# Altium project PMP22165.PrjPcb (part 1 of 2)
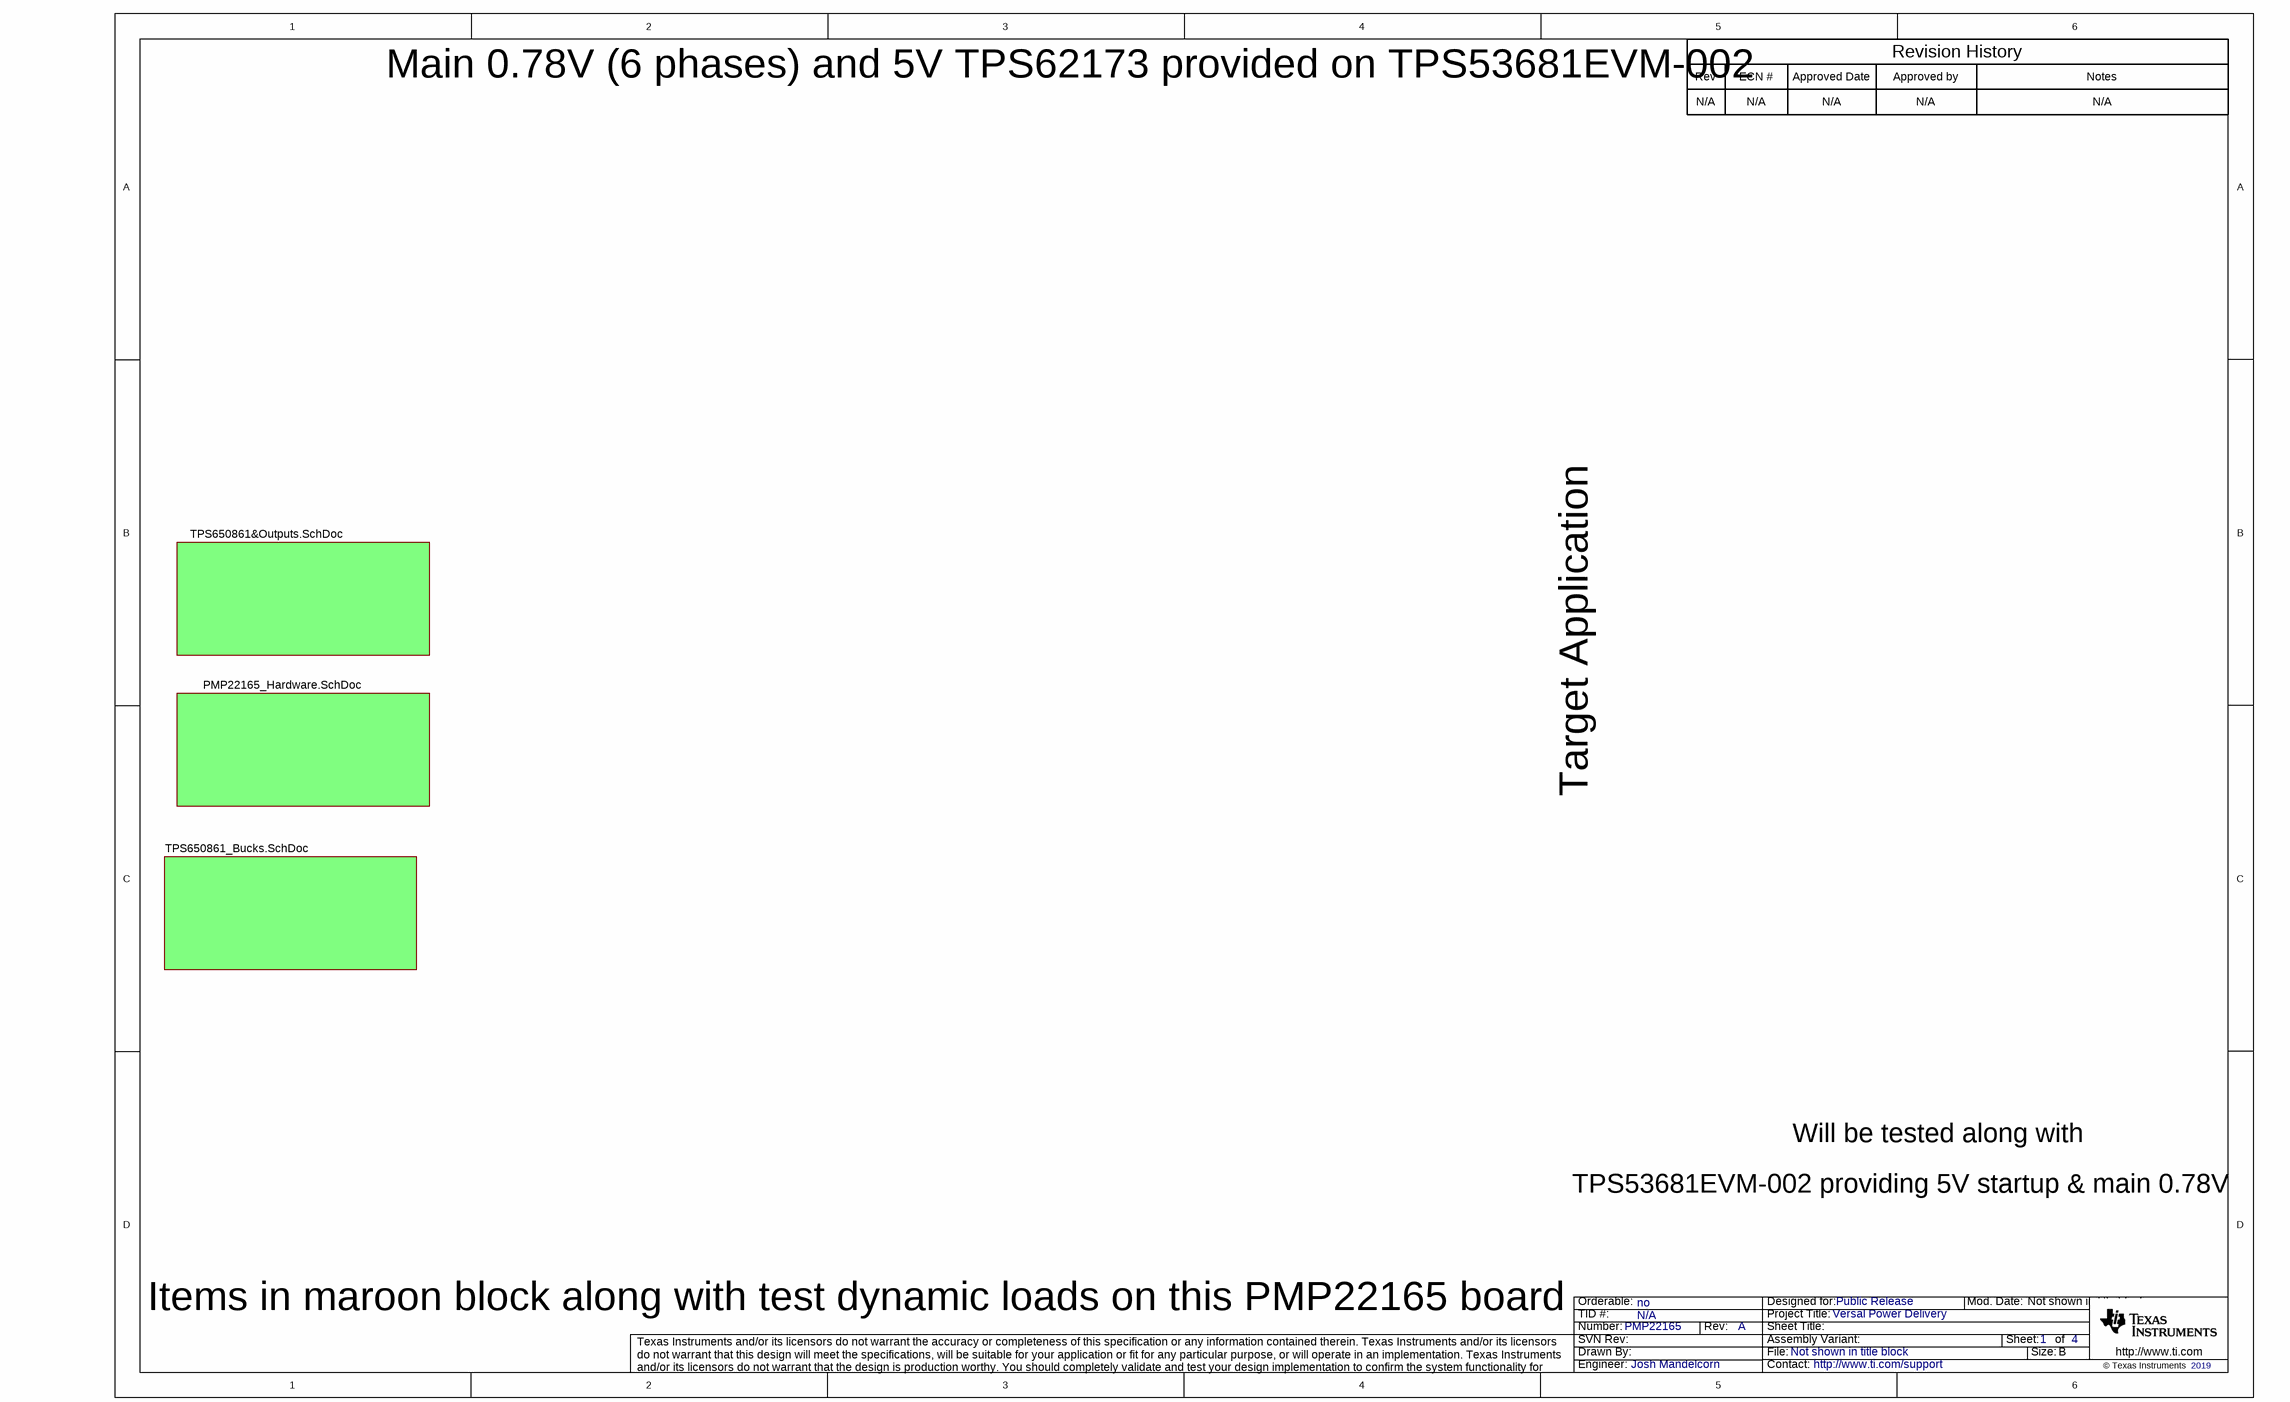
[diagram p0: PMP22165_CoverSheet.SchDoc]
CopyrightYear: 2019; EVM_orderable: no; PCB_Layout: TBD; PCB_Rev: A; PRJ_Customer: Public Release; PRJ_Engineer: Josh Mandelcorn; PRJ_Number: PMP22165; PRJ_Title: Versal Power Delivery; SCH_Rev: A; TechSupport: http://www.ti.com/support; TID: N/A
4 sheets, 234 parts. Net scope: flat (ports and power ports of the same name join across sheets).
Board file: PMP22165_PCB.PcbDoc
Sheets:
  PMP22165_CoverSheet.SchDoc
    Designator = TPS650861&Outputs.SchDoc
    Designator = PMP22165_Hardware.SchDoc
    Designator = TPS650861_Bucks.SchDoc

## Sheet PMP22165_CoverSheet.SchDoc
size 431 x 279 mm; Date: Not shown in title block; ApprovedBy: Not shown in title block; CheckedBy: Not shown in title block; Author: Not shown in title block; CompanyName: Not shown in title block; Engineer: Not shown in title block; Organization: Not shown in title block; Address1: Not shown in title block; Address2: Not shown in title block; Address3: Not shown in title block; Address4: Not shown in title block; DocumentNumber: 1; Revision: Use project parameter SCH_Rev; SheetNumber: 1; SheetTotal: 4; PageSetup: Record=PageOptions¦CenterHorizontal=True¦CenterVertical=True¦PrintScale=1.00¦XCorrection=1.00¦YCorrection=1.00¦PrintKind=0¦BorderSize=5000000¦LeftOffset=0¦BottomOffset=0¦Orientation=2¦PaperLength=1000¦PaperWidth=1000¦Scale=100¦PaperSource=15¦PrintQuality=600¦MediaType=1¦DitherType=10¦PaperKind=Letter¦PrintScaleMode=1

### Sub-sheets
Designator = TPS650861&Outputs.SchDoc: no entries
Designator = PMP22165_Hardware.SchDoc: no entries
Designator = TPS650861_Bucks.SchDoc: no entries

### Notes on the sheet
- Main 0.78V (6 phases) and 5V TPS62173 provided on TPS53681EVM-002
- Rev
- N/A
- ECN #
- Approved Date
- Approved by
- Revision History
- Notes
- Target Application
- Will be tested along with
- TPS53681EVM-002 providing 5V startup & main 0.78V
- Items in maroon block along with test dynamic loads on this PMP22165 board

## Sheet TPS650861&Outputs.SchDoc
size 431 x 279 mm; Date: Not shown in title block; ApprovedBy: Not shown in title block; CheckedBy: Not shown in title block; Author: Not shown in title block; CompanyName: Not shown in title block; Engineer: Not shown in title block; Organization: Not shown in title block; Address1: Not shown in title block; Address2: Not shown in title block; Address3: Not shown in title block; Address4: Not shown in title block; DocumentNumber: 2; Revision: Use project parameter SCH_Rev; SheetNumber: 2; SheetTotal: 4; PageSetup: Record=PageOptions¦CenterHorizontal=True¦CenterVertical=True¦PrintScale=1.00¦XCorrection=1.00¦YCorrection=1.00¦PrintKind=0¦BorderSize=5000000¦LeftOffset=0¦BottomOffset=0¦Orientation=2¦PaperLength=1000¦PaperWidth=1000¦Scale=100¦PaperSource=15¦PrintQuality=600¦MediaType=1¦DitherType=10¦PaperKind=Letter¦PrintScaleMode=1
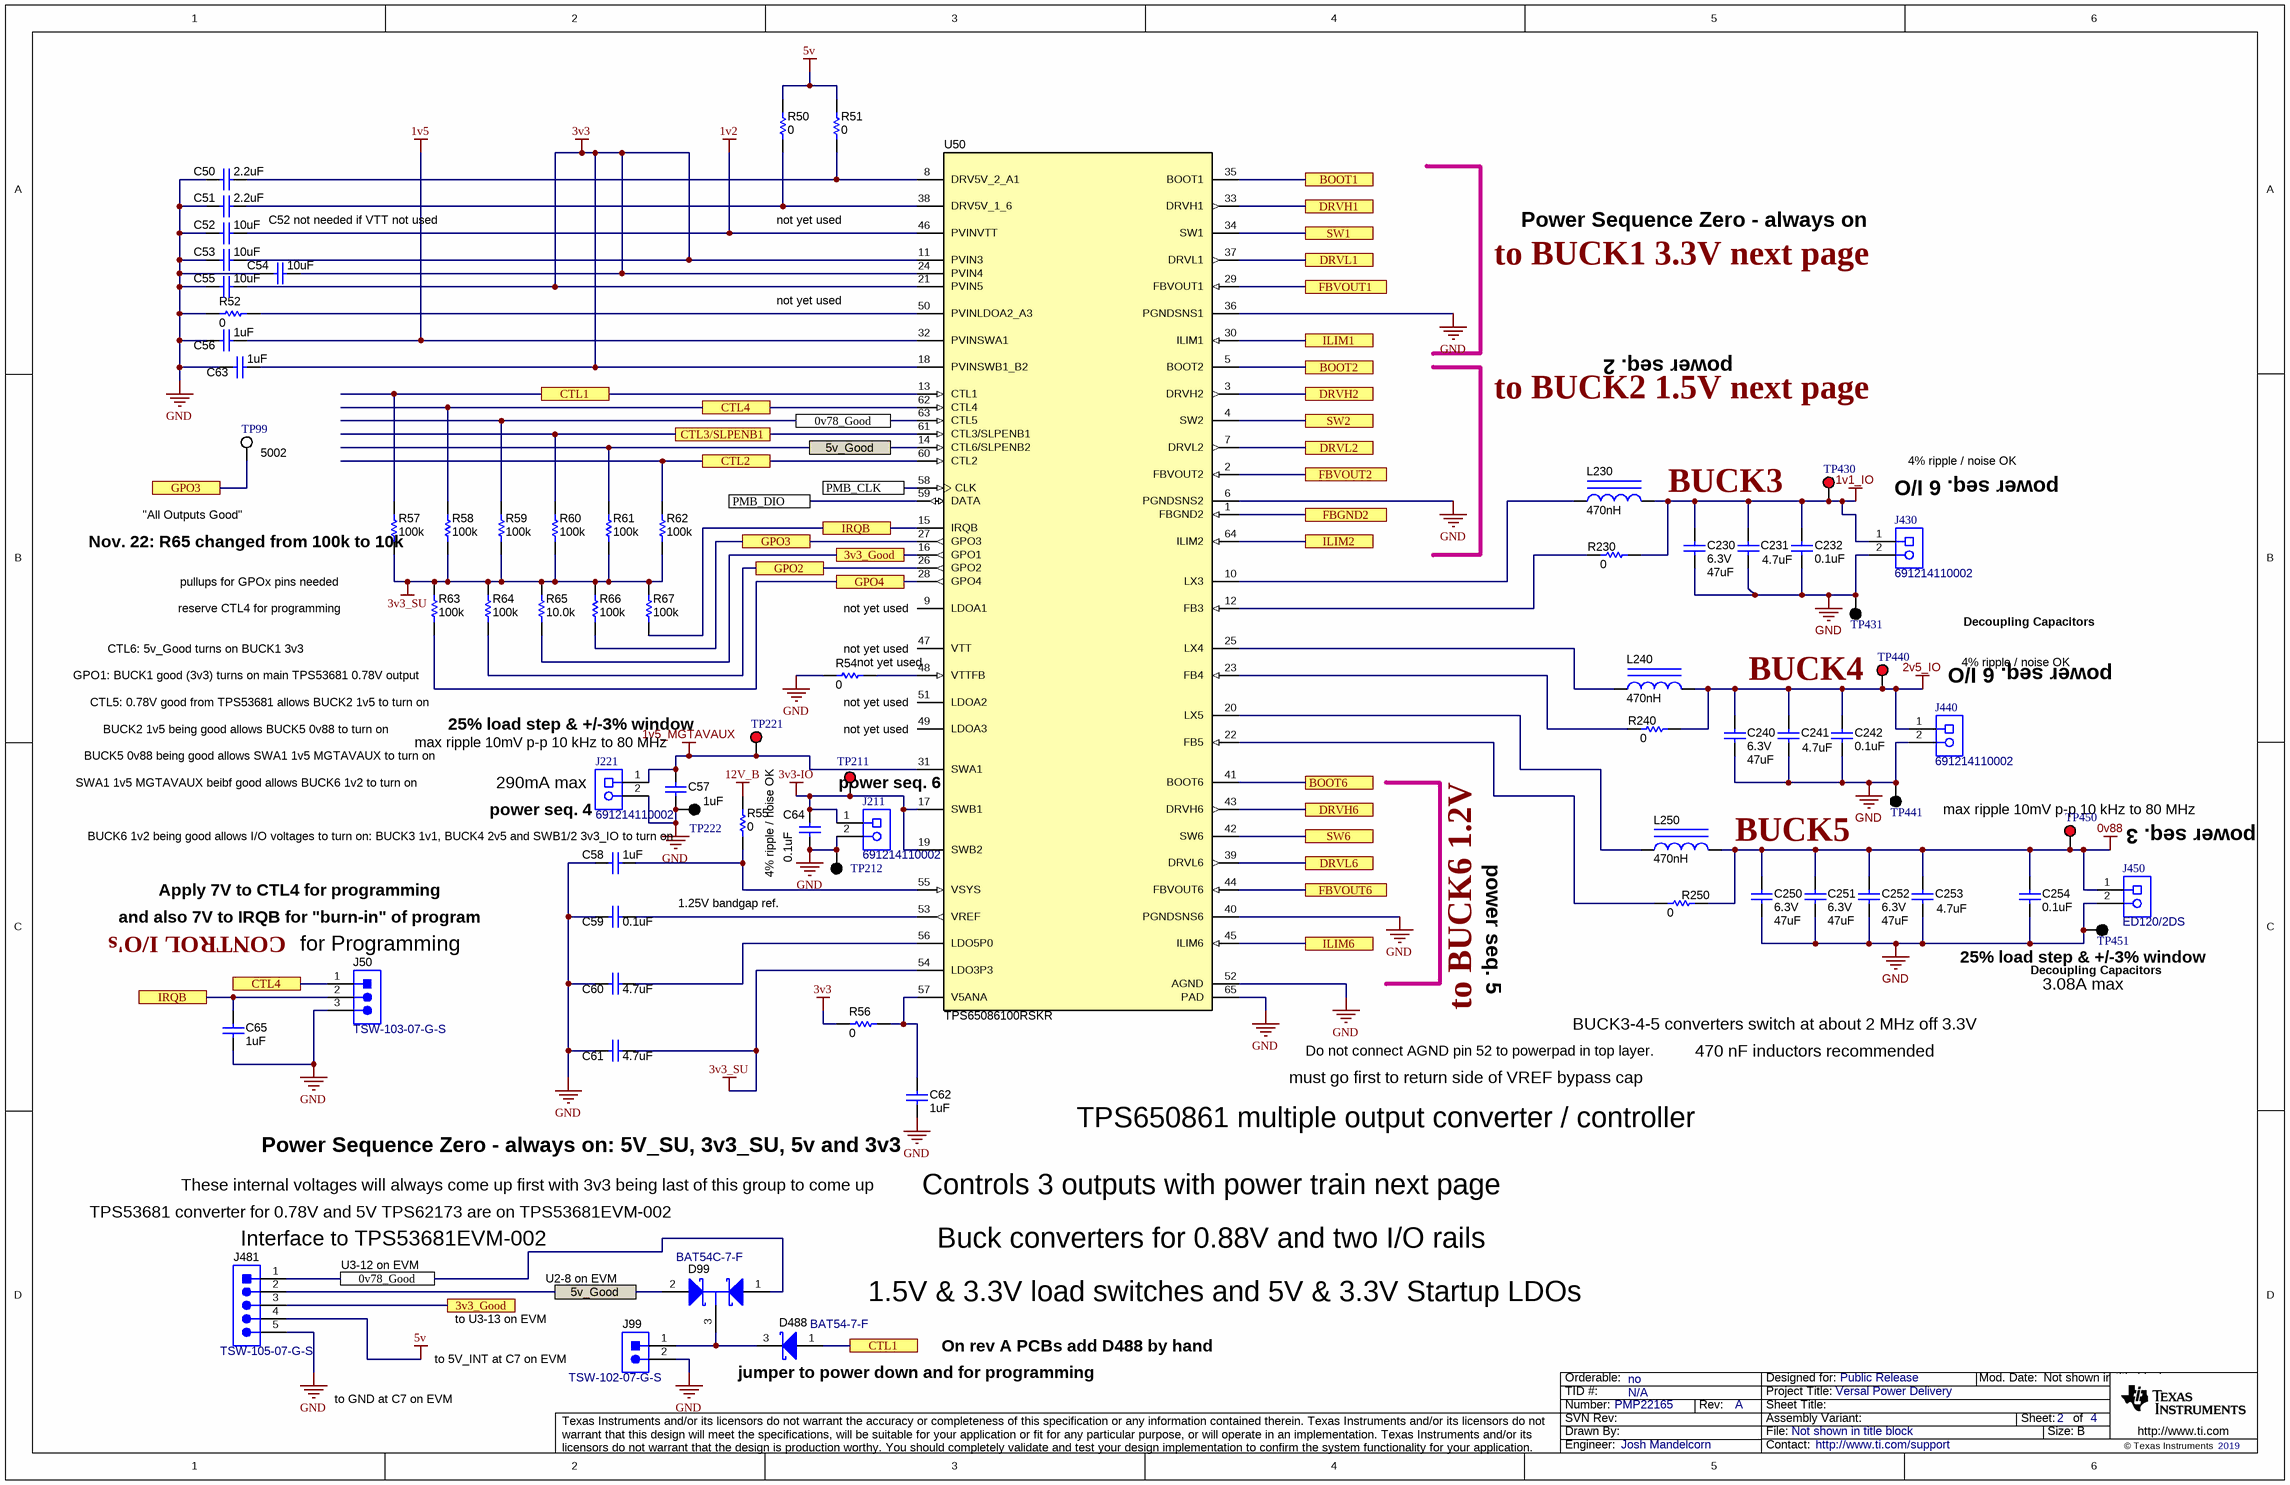
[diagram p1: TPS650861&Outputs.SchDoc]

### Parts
C50  ValueDisplayed: 2.2uF  [0402]  (hidden comment: Capacitor)
C51  ValueDisplayed: 2.2uF  [0402]  (hidden comment: Capacitor)
C52  ValueDisplayed: 10uF  [0402]  (hidden comment: GRM155R61A106ME11)
C53  ValueDisplayed: 10uF  [0402]  (hidden comment: GRM155R61A106ME11)
C54  ValueDisplayed: 10uF  [0402]  (hidden comment: GRM155R61A106ME11)
C55  ValueDisplayed: 10uF  [0402]  (hidden comment: GRM155R61A106ME11)
C56  ValueDisplayed: 1uF  [0402]  (hidden comment: Capacitor)
C57  ValueDisplayed: 1uF  [0402]  (hidden comment: Capacitor)
C58  ValueDisplayed: 1uF  [0402]  (hidden comment: Capacitor)
C59  ValueDisplayed: 0.1uF  [0402]  (hidden comment: Capacitor)
C60  ValueDisplayed: 4.7uF  [0603]  (hidden comment: Capacitor)
C61  ValueDisplayed: 4.7uF  [0603]  (hidden comment: Capacitor)
C62  ValueDisplayed: 1uF  [0402]  (hidden comment: Capacitor)
C63  ValueDisplayed: 1uF  [0402]  (hidden comment: Capacitor)
C64  ValueDisplayed: 0.1uF  [0402]  (hidden comment: Capacitor)
C65  ValueDisplayed: 1uF  [0402]  (hidden comment: Capacitor)
C230  VDC_V: 6.3V  ValueDisplayed: 47uF  [0805_HV]  (hidden comment: GRM21BR60J476ME15L)
C231  value 4.7uF  [0603]  (hidden comment: Capacitor)
C232  ValueDisplayed: 0.1uF  [0402]  (hidden comment: Capacitor)
C240  VDC_V: 6.3V  ValueDisplayed: 47uF  [0805_HV]  (hidden comment: GRM21BR60J476ME15L)
C241  value 4.7uF  [0603]  (hidden comment: Capacitor)
C242  ValueDisplayed: 0.1uF  [0402]  (hidden comment: Capacitor)
C250  VDC_V: 6.3V  ValueDisplayed: 47uF  [0805_HV]  (hidden comment: GRM21BR60J476ME15L)
C251  VDC_V: 6.3V  ValueDisplayed: 47uF  [0805_HV]  (hidden comment: GRM21BR60J476ME15L)
C252  VDC_V: 6.3V  ValueDisplayed: 47uF  [0805_HV]  (hidden comment: GRM21BR60J476ME15L)
C253  value 4.7uF  [0603]  (hidden comment: Capacitor)
C254  ValueDisplayed: 0.1uF  [0402]  (hidden comment: Capacitor)
D99  BAT54C-7-F  [SOT-23]
D488  BAT54-7-F  [SOT-23]
J50  TSW-103-07-G-S  [TSW-103-07-G-S]
J99  TSW-102-07-G-S  [TSW-102-07-G-S]
J211  691214110002  [Wurth_691214110002]
J221  691214110002  [Wurth_691214110002]
J430  691214110002  [Wurth_691214110002]
J440  691214110002  [Wurth_691214110002]
J450  ED120/2DS  [On-Shore_ED120_2DS]
J481  TSW-105-07-G-S  [TSW-105-07-X-S]
L230  ValueDisplayed: 470nH  [WE-MAPI_3020]  (hidden comment: 744383360047)
L240  ValueDisplayed: 470nH  [WE-MAPI_3020]  (hidden comment: 744383360047)
L250  ValueDisplayed: 470nH  [WE-MAPI_3020]  (hidden comment: 744383360047)
R50  ValueDisplayed: 0  [0402]  (hidden comment: Resistor)
R51  ValueDisplayed: 0  [0402]  (hidden comment: Resistor)
R52  ValueDisplayed: 0  [0402]  (hidden comment: Resistor)
R54  ValueDisplayed: 0  [0402]  (hidden comment: Resistor)
R55  ValueDisplayed: 0  [0402]  (hidden comment: Resistor)
R56  ValueDisplayed: 0  [0402]  (hidden comment: Resistor)
R57  Value_Code: 100k  [0402]  (hidden comment: Resistor)
R58  Value_Code: 100k  [0402]  (hidden comment: Resistor)
R59  Value_Code: 100k  [0402]  (hidden comment: Resistor)
R60  Value_Code: 100k  [0402]  (hidden comment: Resistor)
R61  Value_Code: 100k  [0402]  (hidden comment: Resistor)
R62  Value_Code: 100k  [0402]  (hidden comment: Resistor)
R63  Value_Code: 100k  [0402]  (hidden comment: Resistor)
R64  Value_Code: 100k  [0402]  (hidden comment: Resistor)
R65  ValueDisplayed: 10.0k  [0402]  (hidden comment: CRCW040210K0FKED)
R66  Value_Code: 100k  [0402]  (hidden comment: Resistor)
R67  Value_Code: 100k  [0402]  (hidden comment: Resistor)
R230  ValueDisplayed: 0  [0402]  (hidden comment: Resistor)
R240  ValueDisplayed: 0  [0402]  (hidden comment: Resistor)
R250  ValueDisplayed: 0  [0402]  (hidden comment: Resistor)
TP99  5002  [Keystone5002]
TP211  5000  [Keystone5000]  (value not drawn)
TP212  5001  [Keystone5001]  (value not drawn)
TP221  5000  [Keystone5000]  (value not drawn)
TP222  5001  [Keystone5001]  (value not drawn)
TP430  5000  [Keystone5000]  (value not drawn)
TP431  5001  [Keystone5001]  (value not drawn)
TP440  5000  [Keystone5000]  (value not drawn)
TP441  5001  [Keystone5001]  (value not drawn)
TP450  5000  [Keystone5000]  (value not drawn)
TP451  5001  [Keystone5001]  (value not drawn)
U50  TPS65086100RSKR  [RSK0064C]

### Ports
0v78_Good, 3v3_Good, 5v_Good, BOOT1, BOOT2, BOOT6, CTL1, CTL2, CTL3/SLPENB1, CTL4, DRVH1, DRVH2, DRVH6, DRVL1, DRVL2, DRVL6, FBGND2, FBVOUT1, FBVOUT2, FBVOUT6, GPO2, GPO3, GPO4, ILIM1, ILIM2, ILIM6, IRQB, PMB_CLK, PMB_DIO, SW1, SW2, SW6

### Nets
0v88: C250.1 C251.1 C252.1 C253.1 C254.1 J450.1 L250.2 R250.2 TP450.1
1v1_IO: C230.1 C231.1 C232.1 J430.1 L230.2 R230.2 TP430.1
1v2: C52.1 U50.46(PVINVTT)
1v5: C56.1 U50.32(PVINSWA1)
1v5_MGTAVAUX: C57.1 J221.1 TP221.1 U50.31(SWA1)
2v5_IO: C240.1 C241.1 C242.1 J440.1 L240.2 R240.2 TP440.1
3v3: C53.1 C54.1 C55.1 C63.1 R56.2 U50.11(PVIN3) U50.18(PVINSWB1_B2) U50.21(PVIN5) U50.24(PVIN4)
3v3-IO: C64.1 J211.1 TP211.1 U50.17(SWB1) U50.19(SWB2)
3v3_SU: C61.1 R57.2 R58.2 R59.2 R60.2 R61.2 R62.2 R63.1 R64.1 R65.2 R66.1 R67.1 U50.54(LDO3P3)
5v: J481.4 R50.1 R51.1
12V_B: R55.2
GND: C50.2 C51.2 C52.2 C53.2 C54.2 C55.2 C56.2 C57.2 C58.2 C59.2 C60.2 C61.2 C62.2 C63.2 C64.2 C65.2 C230.2 C231.2 C232.2 C240.2 C241.2 C242.2 C250.2 C251.2 C252.2 C253.2 C254.2 J50.3 J99.2 J211.2 J221.2 J430.2 J440.2 J450.2 J481.5 R52.2 R54.2 TP212.1 TP222.1 TP431.1 TP441.1 TP451.1 U50.6(PGNDSNS2) U50.36(PGNDSNS1) U50.40(PGNDSNS6) U50.52(AGND) U50.65(PAD)
0v78_Good: D99.1(A1) J481.1 R59.1 U50.63(CTL5) ; port 0v78_Good
3v3_Good: J481.3 R65.1 U50.16(GPO1) ; port 3v3_Good
5v_Good: D99.2(A2) J481.2 R61.1 U50.14(CTL6/SLPENB2) ; port 5v_Good
BOOT1: U50.35(BOOT1) ; port BOOT1
BOOT2: U50.5(BOOT2) ; port BOOT2
BOOT6: U50.41(BOOT6) ; port BOOT6
CTL1: D488.1(A) R57.1 U50.13(CTL1) ; port CTL1
CTL2: R62.1 U50.60(CTL2) ; port CTL2
CTL3/SLPENB1: R60.1 U50.61(CTL3/SLPENB1) ; port CTL3/SLPENB1
CTL4: J50.1 R58.1 U50.62(CTL4) ; port CTL4
DRVH1: U50.33(DRVH1) ; port DRVH1
DRVH2: U50.3(DRVH2) ; port DRVH2
DRVH6: U50.43(DRVH6) ; port DRVH6
DRVL1: U50.37(DRVL1) ; port DRVL1
DRVL2: U50.7(DRVL2) ; port DRVL2
DRVL6: U50.39(DRVL6) ; port DRVL6
FBGND2: U50.1(FBGND2) ; port FBGND2
FBVOUT1: U50.29(FBVOUT1) ; port FBVOUT1
FBVOUT2: U50.2(FBVOUT2) ; port FBVOUT2
FBVOUT6: U50.44(FBVOUT6) ; port FBVOUT6
GPO2: R64.2 U50.26(GPO2) ; port GPO2
GPO3: R66.2 TP99.1 U50.27(GPO3) ; port GPO3
GPO4: R63.2 U50.28(GPO4) ; port GPO4
ILIM1: U50.30(ILIM1) ; port ILIM1
ILIM2: U50.64(ILIM2) ; port ILIM2
ILIM6: U50.45(ILIM6) ; port ILIM6
IRQB: C65.1 J50.2 R67.2 U50.15(IRQB) ; port IRQB
PMB_CLK: U50.58(CLK) ; port PMB_CLK
PMB_DIO: U50.59(DATA) ; port PMB_DIO
SW1: U50.34(SW1) ; port SW1
SW2: U50.4(SW2) ; port SW2
SW6: U50.42(SW6) ; port SW6
NetC50_1: C50.1 R51.2 U50.8(DRV5V_2_A1)
NetC51_1: C51.1 R50.2 U50.38(DRV5V_1_6)
NetC58_1: C58.1 R55.1 U50.55(VSYS)
NetC59_1: C59.1 U50.53(VREF)
NetC60_1: C60.1 U50.56(LDO5P0)
NetC62_1: C62.1 R56.1 U50.57(V5ANA)
NetD99_3: D99.3(K) D488.3(K) J99.1
NetL230_1: L230.1 U50.10(LX3)
NetL240_1: L240.1 U50.25(LX4)
NetL250_1: L250.1 U50.20(LX5)
NetR52_1: R52.1 U50.50(PVINLDOA2_A3)
NetR54_1: R54.1 U50.48(VTTFB)
NetR230_1: R230.1 U50.12(FB3)
NetR240_1: R240.1 U50.23(FB4)
NetR250_1: R250.1 U50.22(FB5)

Not connected (* = marked no-connect by the designer): U50 9(LDOA1) 47(VTT) 49(LDOA3) 51(LDOA2)

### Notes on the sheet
- C52 not needed if VTT not used
- not yet used
- Power Sequence Zero - always on
- to BUCK1 3.3V next page
- power seq. 2
- to BUCK2 1.5V next page
- BUCK3
- 4% ripple / noise OK
- power seq. 6 I/O
- "All Outputs Good"
- (near R57) Nov. 22: R65 changed from 100k to 10k
- pullups for GPOx pins needed
- reserve CTL4 for programming
- (near U50) not yet used
- Decoupling Capacitors
- CTL6: 5v_Good turns on BUCK1 3v3
- (near R63) GPO1: BUCK1 good (3v3) turns on main TPS53681 0.78V output
- CTL5: 0.78V good from TPS53681 allows BUCK2 1v5 to turn on
- (near R54) not yet used
- BUCK4
- BUCK2 1v5 being good allows BUCK5 0v88 to turn on
- BUCK5 0v88 being good allows SWA1 1v5 MGTAVAUX to turn on
- (near TP221) 25% load step & +/-3% window
- max ripple 10mV p-p 10 kHz to 80 MHz
- SWA1 1v5 MGTAVAUX beibf good allows BUCK6 1v2 to turn on
- BUCK6 1v2 being good allows I/O voltages to turn on: BUCK3 1v1, BUCK4 2v5 and SWB1/2 3v3_IO to turn on
- power seq. 4
- (near J221) 290mA max
- power seq. 6
- (near TP450) max ripple 10mV p-p 10 kHz to 80 MHz
- power seq. 3
- Apply 7V to CTL4 for programming
- 1.25V bandgap ref.
- BUCK5
- CONTROL I/O's
- and also 7V to IRQB for "burn-in" of program
- (near J50) for Programming
- power seq. 5
- (near TP451) 25% load step & +/-3% window
- (near TP451) Decoupling Capacitors
- to BUCK6 1.2V
- BUCK3-4-5 converters switch at about 2 MHz off 3.3V
- (near TP451) 3.08A max
- must go first to return side of VREF bypass cap
- Do not connect AGND pin 52 to powerpad in top layer.
- 470 nF inductors recommended
- (near C62) Power Sequence Zero - always on: 5V_SU, 3v3_SU, 5v and 3v3
- TPS650861 multiple output converter / controller
- TPS53681 converter for 0.78V and 5V TPS62173 are on TPS53681EVM-002
- (near J481) Interface to TPS53681EVM-002
- These internal voltages will always come up first with 3v3 being last of this group to come up
- Controls 3 outputs with power train next page
- Buck converters for 0.88V and two I/O rails
- U3-12 on EVM
- U2-8 on EVM
- 1.5V & 3.3V load switches and 5V & 3.3V Startup LDOs
- to U3-13 on EVM
- to 5V_INT at C7 on EVM
- (near D488) jumper to power down and for programming
- On rev A PCBs add D488 by hand
- to GND at C7 on EVM

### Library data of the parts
C50 C51 = CMP-0006341-2: CAP, CERM, 2.2 uF, 6.3 V, +/- 10%, X5R, 0402; PartNumber: CL05A225KQ5NNNC; Manufacturer: Samsung; Polarized: N; Value: 2.2uF; U/M: EA; Cap_F: 2.2µF; Value1: Unknown; VDC_V: 6.3V; TaMin_C: -55°C; TaMax_C: 85°C; AEC Category: Q200; SizeArea_mm2: 0.5; SizeAreaWB_mm2: 3; SizeX_mm: 1; SizeZ_mm: 0.6
C52-C55 = CMP-0006564-2: CAP, CERM, 10 uF, 10 V, +/- 20%, X5R, 0402; Manufacturer: MuRata; TaMin_C: -55°C; Polarized: N; SizeAreaWB_mm2: 3; Value1: Unknown; U/M: EA; Value: 10uF; TaMax_C: 85°C; SizeZ_mm: 0.6; SizeX_mm: 1; SizeY_mm: 0.5; Value2: 10V; Cap_F: 10µF; AEC Category: Q200
C56 C57 C62 C63 C65 = CMP-0006563-2: CAP, CERM, 1 uF, 10 V, +/- 10%, X5R, 0402; PartNumber: GRM155R61A105KE15D; Manufacturer: MuRata; Polarized: N; Value: 1uF; U/M: EA; Cap_F: 1µF; Value1: Unknown; VDC_V: 10V; TaMin_C: -55°C; TaMax_C: 85°C; AEC Category: Q200; SizeArea_mm2: 0.5; SizeAreaWB_mm2: 3; SizeX_mm: 1; SizeZ_mm: 0.6
C58 = CMP-0006619-2: CAP, CERM, 1 uF, 35 V, +/- 10%, X5R, 0402; PartNumber: GRM155R6YA105KE11D; Manufacturer: MuRata; Polarized: N; Value: 1uF; U/M: EA; Cap_F: 1µF; Value1: Unknown; VDC_V: 35V; TaMin_C: -55°C; TaMax_C: 85°C; AEC Category: Q200; SizeArea_mm2: 0.5; SizeAreaWB_mm2: 3; SizeX_mm: 1; SizeZ_mm: 0.6
C59 C64 C232 C242 C254 = CMP-0006562-2: CAP, CERM, 0.1 uF, 10 V, +/- 10%, X5R, 0402; PartNumber: GRM155R61A104KA01D; Manufacturer: MuRata; Polarized: N; Value: 0.1uF; U/M: EA; Cap_F: 100nF; Value1: Unknown; VDC_V: 10V; TaMin_C: -55°C; TaMax_C: 85°C; AEC Category: Q200; SizeArea_mm2: 0.5; SizeAreaWB_mm2: 3; SizeX_mm: 1; SizeZ_mm: 0.6
C60 C61 = CMP-0007330-5: CAP, CERM, 4.7 uF, 10 V, +/- 20%, X5R, 0603; PartNumber: GRM188R61A475ME15; Manufacturer: MuRata; Polarized: N; Value: 4.7uF; U/M: EA; Cap_F: 4.7µF; Value1: Unknown; VDC_V: 10V; TaMin_C: -55°C; TaMax_C: 85°C; AEC Category: Q200; SizeArea_mm2: 1.28; SizeAreaWB_mm2: 4.68; SizeX_mm: 1.6; SizeY_mm: 0.8; SizeZ_mm: 1
C230 C240 C250-C252 = CMP-0008284-2: CAP, CERM, 47 uF, 6.3 V, +/- 20%, X5R, 0805; Manufacturer: MuRata; TaMin_C: -55°C; Polarized: N; SizeAreaWB_mm2: 6.75; Value1: Unknown; U/M: EA; Value: 47uF; TaMax_C: 85°C; SizeZ_mm: 1.45; SizeX_mm: 2; SizeY_mm: 1.25; Cap_Case: 0805; SizeArea_mm2: 2.5; Cap_F: 47µF; AEC Category: Q200
C231 C241 C253 = CMP-0007312-5: CAP, CERM, 4.7 uF, 6.3 V, +/- 20%, X5R, 0603; PartNumber: GRM188R60J475ME19D; Manufacturer: MuRata; Polarized: N; U/M: EA; Cap_F: 4.7µF; ESR_ohm: 1m; Value1: 0.001 ohm; VDC_V: 6.3V; TaMin_C: -55°C; TaMax_C: 85°C; AEC Category: Q200; SizeArea_mm2: 1.28; SizeAreaWB_mm2: 4.68; SizeX_mm: 1.6; SizeY_mm: 0.8; SizeZ_mm: 1
D99 = CMP-0028453-2: Diode, Schottky, 30 V, 0.2 A, SOT-23; Manufacturer: Diodes Inc.; Vr_V: 30V; Green_Lifecycle: Active; Vf_V: 650mV; Value: 30V; SizeZ_mm: 1.1; SizeAreaWB_mm2: 14; TJmax_C: 125°C; Io_A: 200mA; Value2: 0.65V; SizeY_mm: 3; AEC Category: Q101; SizeX_mm: 2.5; Green_REACh: Passed; Value1: 0.2A; SizeArea_mm2: 7.5
D488 = CMP-0028451-1: Diode, Schottky, 30 V, 0.2 A, SOT-23; Manufacturer: Diodes Inc.; Io_A: 200mA; Green_Lifecycle: Active; SizeAreaWB_mm2: 14; Vr_V: 30V; Green_REACh: Passed; Value1: 0.2A; TJmax_C: 125°C; U/M: EA; Value: 30V; SizeZ_mm: 1.1; SizeX_mm: 2.5; SizeY_mm: 3; Vf_V: 650mV; Value2: 0.65V; SizeArea_mm2: 7.5; AEC Category: Q101
J50 = CMP-0075407-2: Header, 100mil, 3x1, Gold, TH; Manufacturer: Samtec; Pitch_mm: 2.54; Cert_VDE: N; Gender: Male; Cert_CSA: Y; Voltage_V: 550V; Green_REACh: Passed; Current_A: 6.3A; Green_Lifecycle: Active; Row_Count: 1
J99 = CMP-0075405-3: Header, 100mil, 2x1, Gold, TH; Manufacturer: Samtec; Current_A: 6.3A; Green_Lifecycle: Active; Pitch_mm: 2.54; Cert_CSA: Y; Cert_VDE: N; Green_REACh: Passed; Row_Count: 1; Gender: Male; Voltage_V: 550V
J211 J221 J430 J440 = CMP-0054825-2: Terminal Block, 3.5mm, 2x1, Tin, TH; Manufacturer: Wurth Elektronik; Pitch_mm: 3.5; CT: TRUE; CNHeader: FALSE; Voltage_V: 300V; Gender: Female; Cert_UL: Y; Row_Count: 1; Current_A: 10A
J450 = CMP-0074910-1: Terminal Block, 5.08 mm, 2x1, Brass, TH; Manufacturer: On-Shore Technology; Cert_VDE: Y; CNHeader: False; Current_A: 15A; Green_Lifecycle: Not Set; Shrouded: N; Gender: Female; Green_REACh: Incomplete; Voltage_V: 300V; Row_Count: 1; Pitch_mm: 5.08; CT: True
J481 = CMP-0075411-1: Header, 100mil, 5x1, Gold, TH; Manufacturer: Samtec; Pitch_mm: 2.54; Cert_VDE: N; Gender: Male; Cert_CSA: Y; Voltage_V: 550V; Green_REACh: Passed; Current_A: 6.3A; CT: False; Green_Lifecycle: Active; Row_Count: 1; CNHeader: True
L230 L240 L250 = CMP-0064156-1: Inductor, Wirewound, 470 nH, 4.8 A, 0.018 ohm, SMD; Manufacturer: Wurth Elektronik; Isat: 8A @ 20% inductance drop; Irms: 4.8A @ 40C rise; Green_Lifecycle: Active; SizeAreaWB_mm2: 16; DCR_ohm: 0.018; Green_REACh: Passed; Value: 470nH; Imax_A: 4.8A; SizeZ_mm: 2; SizeX_mm: 3; SizeArea_mm2: 9; AEC Qualified: N; AEC Category: Q200
R50-R52 R54-R56 R230 R240 R250 = CMP-0026822-3: RES, 0, 5%, 0.063 W, AEC-Q200 Grade 0, 0402; PartNumber: CRCW04020000Z0ED; Manufacturer: Vishay-Dale; Value: 0; Value_Code: 0000; Power_W: 63mW; Value2: 0.063W; VDC_V: 50V; TempCo: 200 ppm/C; EIA_Code: E24; AEC Category: Q200; AEC Qualified: Y; SizeArea_mm2: 0.5; SizeX_mm: 1; SizeZ_mm: 0.6
R57-R64 R66 R67 = CMP-0026823-3: RES, 100 k, 5%, 0.063 W, AEC-Q200 Grade 0, 0402; PartNumber: CRCW0402100KJNED; Manufacturer: Vishay-Dale; Value: 100k; Power_W: 63mW; Value2: 0.063W; VDC_V: 50V; TempCo: 200 ppm/C; EIA_Code: E24; AEC Category: Q200; AEC Grade: 0; AEC Qualified: Y; SizeArea_mm2: 0.5; SizeX_mm: 1; SizeZ_mm: 0.6
R65 = CMP-0025958-3: RES, 10.0 k, 1%, 0.063 W, AEC-Q200 Grade 0, 0402; Manufacturer: Vishay-Dale; Power_W: 63mW; TempCo: 100 ppm/C; Value_Code: 10k0; Value: 10.0k; EIA_Code: E96; Res_ohm: 10k; SizeX_mm: 1; SizeY_mm: 0.5; SizeZ_mm: 0.6; Value2: 0.063W; AEC Qualified: Y; VDC_V: 50V; AEC Category: Q200; AEC Grade: 0
TP99 = CMP-0055139-1: Test Point, Miniature, White, TH; Manufacturer: Keystone; CNHeader: FALSE; Green_Lifecycle: Active; Green_REACh: Passed; ContactFinish: Silver; CT: TRUE
TP211 TP221 TP430 TP440 TP450 = CMP-0055137-1: Test Point, Miniature, Red, TH; Manufacturer: Keystone; CNHeader: FALSE; Green_Lifecycle: Active; Green_REACh: Passed; ContactFinish: Silver; CT: TRUE
TP212 TP222 TP431 TP441 TP451 = CMP-0055138-1: Test Point, Miniature, Black, TH; Manufacturer: Keystone; CNHeader: FALSE; Green_Lifecycle: Active; Green_REACh: Passed; ContactFinish: Silver; CT: TRUE
U50 = CMP-0079628-1: Configurable Multi-Rail PMIC for 2S & 3S Li-Ion Battery-Operated Devices or Non Battery Operated, RSK0064C (VQFN-64); Alternate PartNumber: TPS65086100RSKT; Alternate Manufacturer: Texas Instruments; SizeAreaWB_mm2: 100; SizeZ_mm: 1; SizeX_mm: 8; SizeArea_mm2: 64; CompType: IC; AEC Qualified: N; AEC Category: Q200

## Sheet PMP22165_Hardware.SchDoc
size 431 x 279 mm; Date: Not shown in title block; ApprovedBy: Not shown in title block; CheckedBy: Not shown in title block; Author: Not shown in title block; CompanyName: Not shown in title block; Engineer: Not shown in title block; Organization: Not shown in title block; Address1: Not shown in title block; Address2: Not shown in title block; Address3: Not shown in title block; Address4: Not shown in title block; DocumentNumber: 4; Revision: Use project parameter SCH_Rev; SheetNumber: 4; SheetTotal: 4; PageSetup: Record=PageOptions¦CenterHorizontal=True¦CenterVertical=True¦PrintScale=1.00¦XCorrection=1.00¦YCorrection=1.00¦PrintKind=0¦BorderSize=5000000¦LeftOffset=0¦BottomOffset=0¦Orientation=2¦PaperLength=1000¦PaperWidth=1000¦Scale=100¦PaperSource=15¦PrintQuality=600¦MediaType=1¦DitherType=10¦PaperKind=Letter¦PrintScaleMode=1
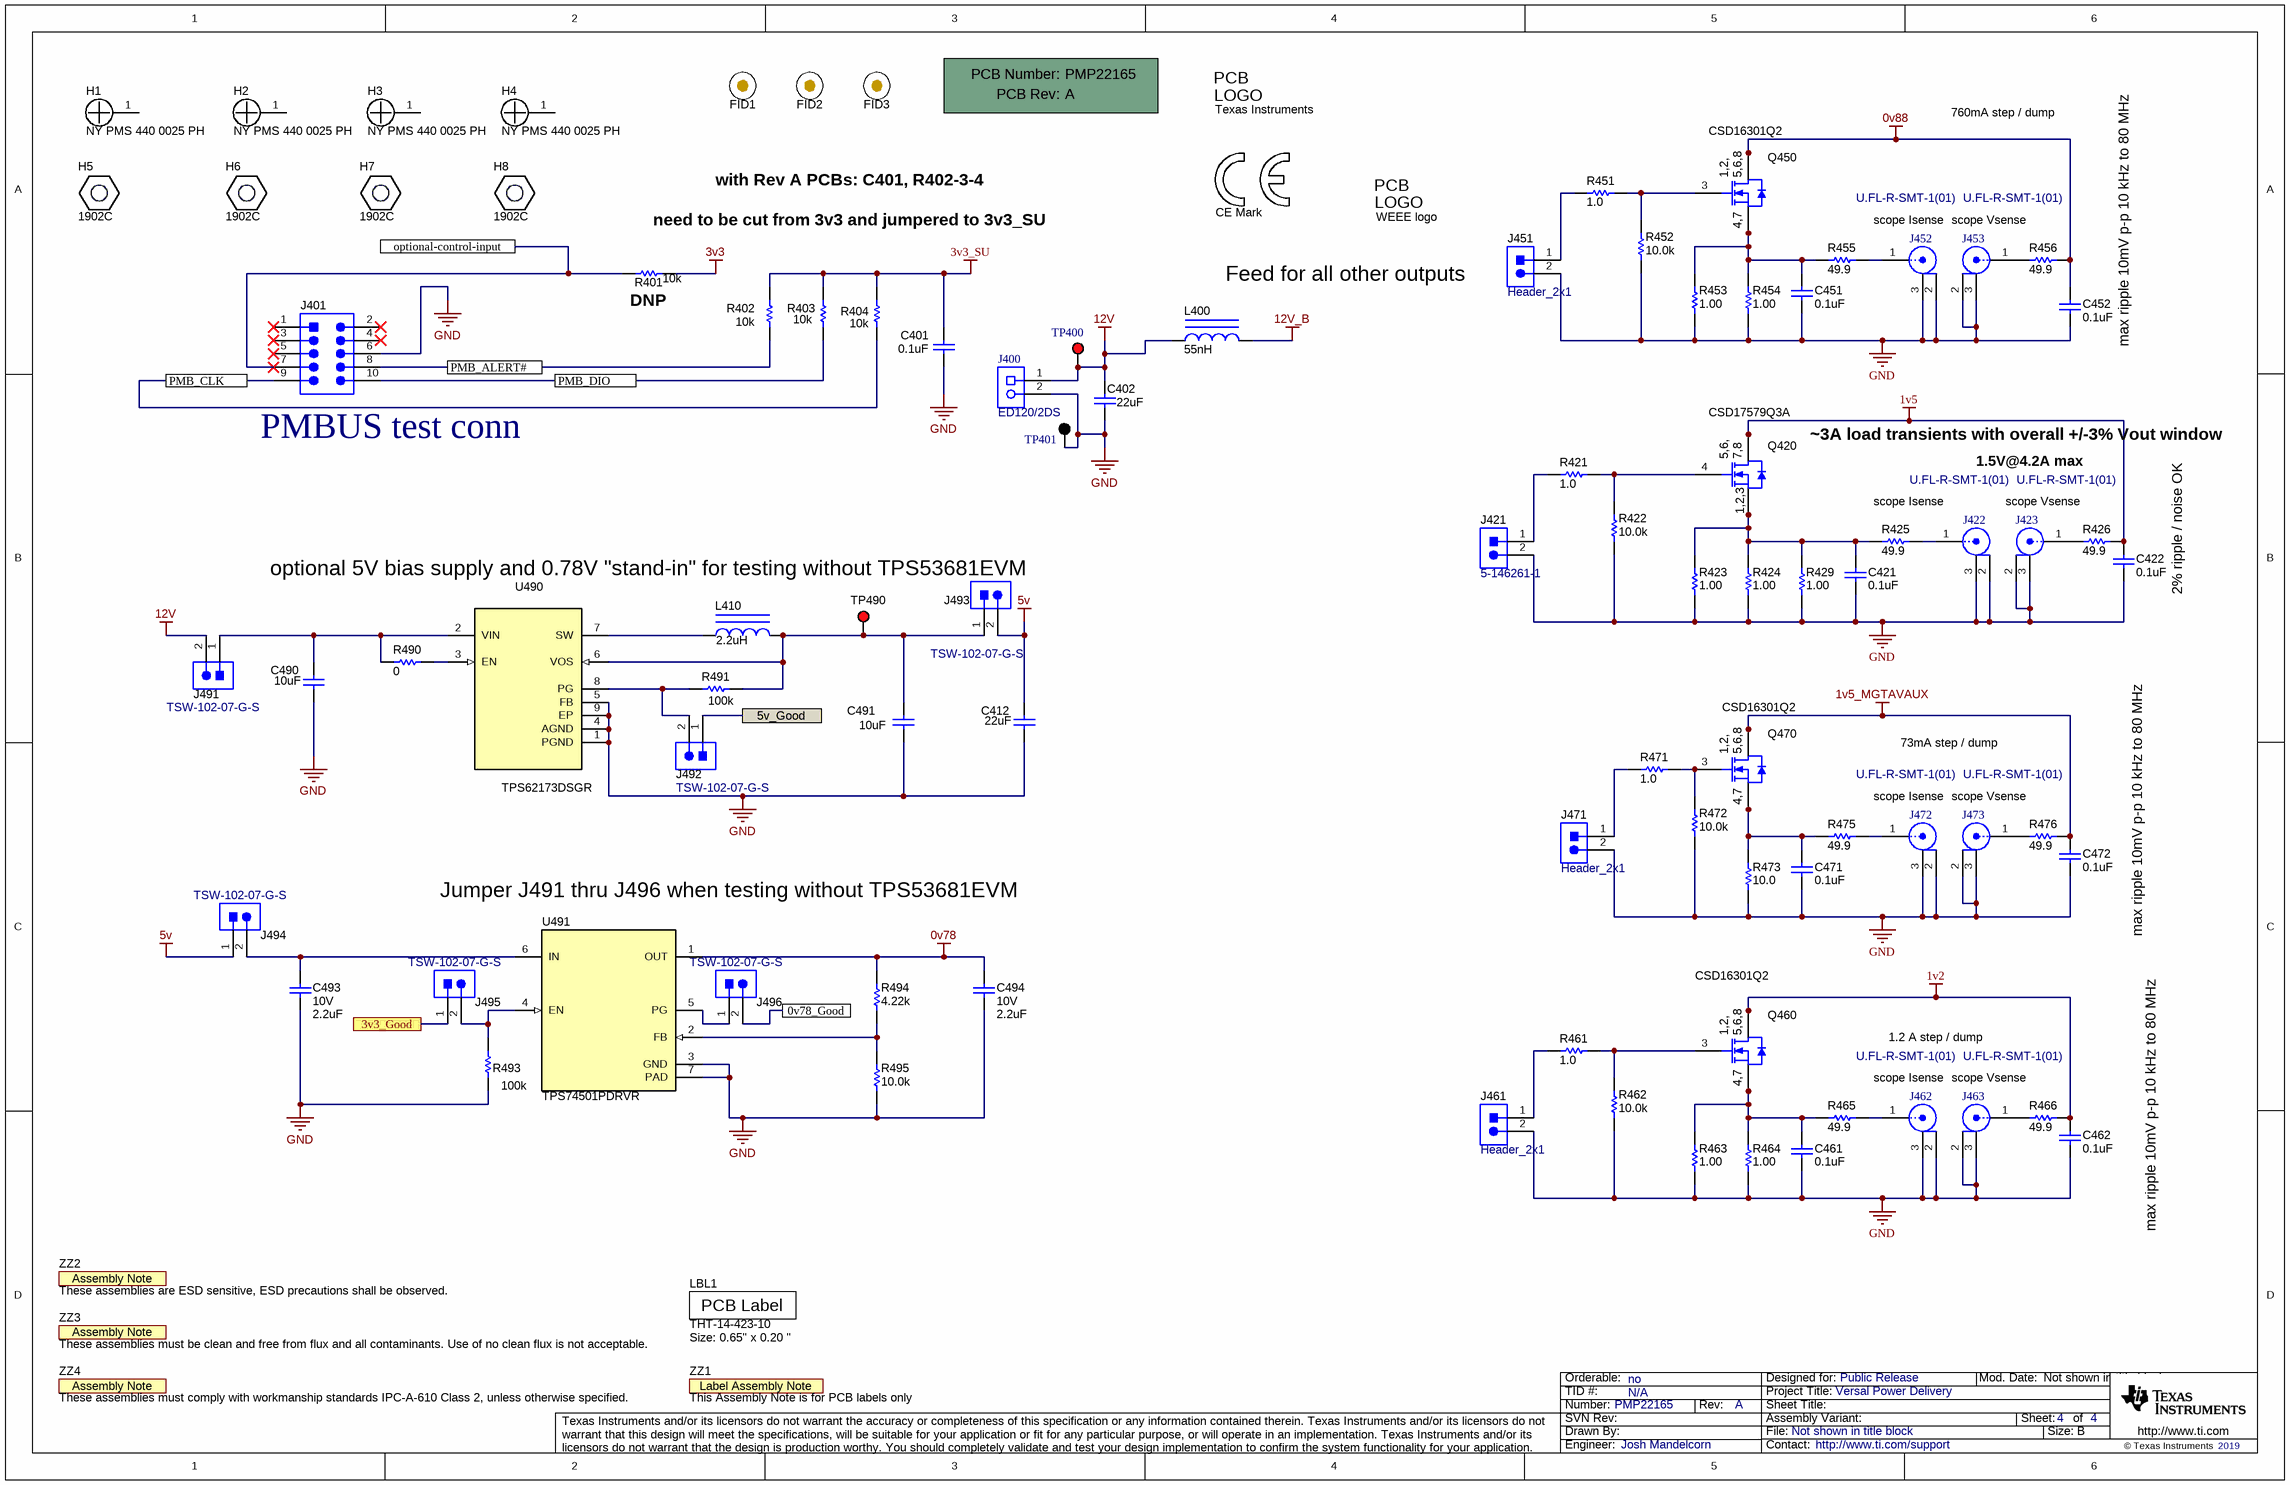
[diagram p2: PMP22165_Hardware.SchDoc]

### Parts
!PCB  Printed Circuit Board  (value not drawn)  (mechanical)
C401  ValueDisplayed: 0.1uF  [0603]  (hidden comment: 06035C104KAT2A)
C402  ValueDisplayed: 22uF  [1206_180]  (hidden comment: GRM31CR61C226KE15L)
C412  ValueDisplayed: 22uF  [0805_HV]  (hidden comment: C2012X5R0J226M085AB)
C421  ValueDisplayed: 0.1uF  [0402]  (hidden comment: GCM155R71H104KE02D)
C422  ValueDisplayed: 0.1uF  [0402]  (hidden comment: GCM155R71H104KE02D)
C451  ValueDisplayed: 0.1uF  [0402]  (hidden comment: Capacitor)
C452  ValueDisplayed: 0.1uF  [0402]  (hidden comment: GCM155R71H104KE02D)
C461  ValueDisplayed: 0.1uF  [0402]  (hidden comment: Capacitor)
C462  ValueDisplayed: 0.1uF  [0402]  (hidden comment: Capacitor)
C471  ValueDisplayed: 0.1uF  [0402]  (hidden comment: Capacitor)
C472  ValueDisplayed: 0.1uF  [0402]  (hidden comment: Capacitor)
C490  ValueDisplayed: 10uF  [0603]  (hidden comment: C1608X5R1E106M080AC)
C491  ValueDisplayed: 10uF  [0805]  (hidden comment: C2012X5R1E106K125AB)
C493  VDC_V: 10V  ValueDisplayed: 2.2uF  [0603]  (hidden comment: CGA3E3X5R1A225K080AB)
C494  VDC_V: 10V  ValueDisplayed: 2.2uF  [0603]  (hidden comment: CGA3E3X5R1A225K080AB)
FID1  Fiducial  [Fiducial10-20]  (value not drawn)
FID2  Fiducial  [Fiducial10-20]  (value not drawn)
FID3  Fiducial  [Fiducial10-20]  (value not drawn)
H1  NY PMS 440 0025 PH  [NY PMS 440 0025 PH]
H2  NY PMS 440 0025 PH  [NY PMS 440 0025 PH]
H3  NY PMS 440 0025 PH  [NY PMS 440 0025 PH]
H4  NY PMS 440 0025 PH  [NY PMS 440 0025 PH]
H5  1902C  [Keystone_1902C]
H6  1902C  [Keystone_1902C]
H7  1902C  [Keystone_1902C]
H8  1902C  [Keystone_1902C]
J400  ED120/2DS  [On-Shore_ED120_2DS]
J401  TSW-105-07-G-D  [TSW-105-07-G-D]  (value not drawn)
J421  5-146261-1  [CONN_5-146261-1]
J422  U.FL-R-SMT-1(01)  [CONN_UFL-R-SMT-1]
J423  U.FL-R-SMT-1(01)  [CONN_UFL-R-SMT-1]
J451  Header_2x1  [CONN_5-146261-1]
J452  U.FL-R-SMT-1(01)  [CONN_UFL-R-SMT-1]
J453  U.FL-R-SMT-1(01)  [CONN_UFL-R-SMT-1]
J461  Header_2x1  [CONN_5-146261-1]
J462  U.FL-R-SMT-1(01)  [CONN_UFL-R-SMT-1]
J463  U.FL-R-SMT-1(01)  [CONN_UFL-R-SMT-1]
J471  Header_2x1  [CONN_5-146261-1]
J472  U.FL-R-SMT-1(01)  [CONN_UFL-R-SMT-1]
J473  U.FL-R-SMT-1(01)  [CONN_UFL-R-SMT-1]
J491  TSW-102-07-G-S  [TSW-102-07-G-S]
J492  TSW-102-07-G-S  [TSW-102-07-G-S]
J493  TSW-102-07-G-S  [TSW-102-07-G-S]
J494  TSW-102-07-G-S  [TSW-102-07-G-S]
J495  TSW-102-07-G-S  [TSW-102-07-G-S]
J496  TSW-102-07-G-S  [TSW-102-07-G-S]
L400  ValueDisplayed: 55nH  [HCB65-550X]  (hidden comment: HCB65-550X)
L410  ValueDisplayed: 2.2uH  [XPL2010]  (hidden comment: XPL2010-222MLB)
LBL1  THT-14-423-10  Note: Size: 0.65" x 0.20 "  [Label_650x200]
Logo1  Texas Instruments  [TI_Stacked_Overlay_Small]  (no BOM)
Logo2  CE Mark  [CE_Mark_5mm]  (no BOM)
Logo4  WEEE logo  [WEEE_Minimum]  (no BOM)
Q420  PartNumber: CSD17579Q3A  [DNH0008A]  (hidden comment: MOSFET_N_D56789G4S123)
Q450  PartNumber: CSD16301Q2  [DQK0006C]  (hidden comment: MOSFET_N_D12568G3S47)
Q460  PartNumber: CSD16301Q2  [DQK0006C]  (hidden comment: MOSFET_N_D12568G3S47)
Q470  PartNumber: CSD16301Q2  [DQK0006C]  (hidden comment: MOSFET_N_D12568G3S47)
R401  value 10k  [0603]  (hidden comment: CRCW060310K0JNEA)
R402  value 10k  [0603]  (hidden comment: CRCW060310K0JNEA)
R403  value 10k  [0603]  (hidden comment: CRCW060310K0JNEA)
R404  value 10k  [0603]  (hidden comment: CRCW060310K0JNEA)
R421  ValueDisplayed: 1.0  [0402]  (hidden comment: Resistor)
R422  ValueDisplayed: 10.0k  [0402]  (hidden comment: Resistor)
R423  ValueDisplayed: 1.00  [1206]  (hidden comment: Resistor)
R424  ValueDisplayed: 1.00  [1206]  (hidden comment: Resistor)
R425  ValueDisplayed: 49.9  [0402]  (hidden comment: Resistor)
R426  ValueDisplayed: 49.9  [0402]  (hidden comment: Resistor)
R429  ValueDisplayed: 1.00  [1206]  (hidden comment: Resistor)
R451  ValueDisplayed: 1.0  [0402]  (hidden comment: Resistor)
R452  ValueDisplayed: 10.0k  [0402]  (hidden comment: Resistor)
R453  ValueDisplayed: 1.00  [1206]  (hidden comment: Resistor)
R454  ValueDisplayed: 1.00  [1206]  (hidden comment: Resistor)
R455  ValueDisplayed: 49.9  [0402]  (hidden comment: Resistor)
R456  ValueDisplayed: 49.9  [0402]  (hidden comment: Resistor)
R461  ValueDisplayed: 1.0  [0402]  (hidden comment: Resistor)
R462  ValueDisplayed: 10.0k  [0402]  (hidden comment: Resistor)
R463  ValueDisplayed: 1.00  [1206]  (hidden comment: Resistor)
R464  ValueDisplayed: 1.00  [1206]  (hidden comment: Resistor)
R465  ValueDisplayed: 49.9  [0402]  (hidden comment: Resistor)
R466  ValueDisplayed: 49.9  [0402]  (hidden comment: Resistor)
R471  ValueDisplayed: 1.0  [0402]  (hidden comment: Resistor)
R472  ValueDisplayed: 10.0k  [0402]  (hidden comment: Resistor)
R473  ValueDisplayed: 10.0  [1206]  (hidden comment: CRCW120610R0FKEA)
R475  ValueDisplayed: 49.9  [0402]  (hidden comment: CRCW040249R9FKED)
R476  ValueDisplayed: 49.9  [0402]  (hidden comment: CRCW040249R9FKED)
R490  ValueDisplayed: 0  [0603]  (hidden comment: CRCW06030000Z0EA)
R491  ValueDisplayed: 100k  [0603]  (hidden comment: CRCW0603100KFKEA)
R493  ValueDisplayed: 100k  [0603]  (hidden comment: CRCW0603100KFKEA)
R494  ValueDisplayed: 4.22k  [0402]  (hidden comment: CRCW04024K22FKED)
R495  ValueDisplayed: 10.0k  [0402]  (hidden comment: CRCW040210K0FKED)
TP400  5000  [Keystone5000]  (value not drawn)
TP401  5001  [Keystone5001]  (value not drawn)
TP490  (no value)  [Keystone5005]
U490  TPS62173DSGR  [DSG0008A]
U491  TPS74501PDRVR  [DRV0006A]
ZZ1  This Assembly Note is for PCB labels only  [AssemblyNoteLabel]  (no BOM)
ZZ2  These assemblies are ESD sensitive, ESD precautions shall be observed.  [AssemblyNote]  (no BOM)
ZZ3  These assemblies must be clean and free from flux and all contaminants. Use of no clean flux is not acceptable.  [AssemblyNote]  (no BOM)
ZZ4  These assemblies must comply with workmanship standards IPC-A-610 Class 2, unless otherwise specified.  [AssemblyNote]  (no BOM)

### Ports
0v78_Good, 3v3_Good, 5v_Good, optional-control-input, PMB_ALERT#, PMB_CLK, PMB_DIO

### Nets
0v78: C494.1 R494.2 U491.1(OUT)
0v88: C452.1 Q450.1(D) Q450.2(D) Q450.5(D) Q450.6(D) Q450.8(D) R456.2
1v2: C462.1 Q460.1(D) Q460.2(D) Q460.5(D) Q460.6(D) Q460.8(D) R466.2
1v5: C422.1 Q420.5(D) Q420.6(D) Q420.7(D) Q420.8(D) Q420.9(D) R426.2
1v5_MGTAVAUX: C472.1 Q470.1(D) Q470.2(D) Q470.5(D) Q470.6(D) Q470.8(D) R476.2
3v3: R401.2
3v3_SU: C401.1 R402.2 R403.2 R404.2
5v: C412.1 J493.2 J494.1
12V: C402.2 J400.1 J491.2 L400.1 TP400.1
12V_B: L400.2
GND: C401.2 C402.1 C412.2 C421.2 C422.2 C451.2 C452.2 C461.2 C462.2 C471.2 C472.2 C490.2 C491.2 C493.2 C494.2 J400.2 J401.6 J421.2 J422.2 J422.3 J423.2 J423.3 J451.2 J452.2 J452.3 J453.2 J453.3 J461.2 J462.2 J462.3 J463.2 J463.3 J471.2 J472.2 J472.3 J473.2 J473.3 R422.1 R423.1 R424.1 R429.1 R452.1 R453.1 R454.1 R462.1 R463.1 R464.1 R472.1 R473.1 R493.1 R495.1 TP401.1 U490.1(PGND) U490.4(AGND) U490.5(FB) U490.9(EP) U491.3(GND) U491.7(PAD)
0v78_Good: J496.2 ; port 0v78_Good
3v3_Good: J495.1 ; port 3v3_Good
5v_Good: J492.1 ; port 5v_Good
optional-control-input: J401.7 R401.1 ; port optional-control-input
PMB_ALERT#: J401.8 R402.1 ; port PMB_ALERT#
PMB_CLK: J401.9 R404.1 ; port PMB_CLK
PMB_DIO: J401.10 R403.1 ; port PMB_DIO
NetC421_1: C421.1 Q420.1(S) Q420.2(S) Q420.3(S) R423.2 R424.2 R425.1 R429.2
NetC451_1: C451.1 Q450.4(S) Q450.7(S) R453.2 R454.2 R455.1
NetC461_1: C461.1 Q460.4(S) Q460.7(S) R463.2 R464.2 R465.1
NetC471_1: C471.1 Q470.4(S) Q470.7(S) R473.2 R475.1
NetC490_1: C490.1 J491.1 R490.2 U490.2(VIN)
NetC491_1: C491.1 J493.1 L410.2 R491.2 TP490.1 U490.6(VOS)
NetC493_1: C493.1 J494.2 U491.6(IN)
NetJ421_1: J421.1 R421.1
NetJ422_1: J422.1 R425.2
NetJ423_1: J423.1 R426.1
NetJ451_1: J451.1 R451.1
NetJ452_1: J452.1 R455.2
NetJ453_1: J453.1 R456.1
NetJ461_1: J461.1 R461.1
NetJ462_1: J462.1 R465.2
NetJ463_1: J463.1 R466.1
NetJ471_1: J471.1 R471.1
NetJ472_1: J472.1 R475.2
NetJ473_1: J473.1 R476.1
NetJ492_2: J492.2 R491.1 U490.8(PG)
NetJ495_2: J495.2 R493.2 U491.4(EN)
NetJ496_1: J496.1 U491.5(PG)
NetL410_1: L410.1 U490.7(SW)
NetQ420_4: Q420.4(G) R421.2 R422.2
NetQ450_3: Q450.3(G) R451.2 R452.2
NetQ460_3: Q460.3(G) R461.2 R462.2
NetQ470_3: Q470.3(G) R471.2 R472.2
NetR490_1: R490.1 U490.3(EN)
NetR494_1: R494.1 R495.2 U491.2(FB)

Not connected (* = marked no-connect by the designer): H1 1; H2 1; H3 1; H4 1; J401 1* 2* 3* 4* 5*

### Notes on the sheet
- 760mA step / dump
- with Rev A PCBs: C401, R402-3-4
- (near R401) need to be cut from 3v3 and jumpered to 3v3_SU
- scope Isense
- scope Vsense
- max ripple 10mV p-p 10 kHz to 80 MHz
- (near R401) DNP
- Feed for all other outputs
- ~3A load transients with overall +/-3% Vout window
- (near J401) PMBUS test conn
- 1.5V@4.2A max
- optional 5V bias supply and 0.78V "stand-in" for testing without TPS53681EVM
- 2% ripple / noise OK
- 73mA step / dump
- Jumper J491 thru J496 when testing without TPS53681EVM
- 1.2 A step / dump

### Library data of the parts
!PCB = CMP-0003618-2: Manufacturer: Any; PartNumber: PMP22165
C401 = CMP-0006802-4: CAP, CERM, 0.1 uF, 50 V, +/- 10%, X7R, 0603; Manufacturer: AVX; Polarized: N; Value: 0.1uF; U/M: EA; Cap_F: 100nF; Value1: Unknown; VDC_V: 50V; TaMin_C: -55°C; TaMax_C: 125°C; AEC Category: Q200; SizeArea_mm2: 1.28; SizeAreaWB_mm2: 4.68; SizeX_mm: 1.6; SizeY_mm: 0.8; SizeZ_mm: 1
C402 = CMP-0008946-2: CAP, CERM, 22 uF, 16 V, +/- 10%, X5R, 1206; Manufacturer: MuRata; Polarized: N; Value: 22uF; U/M: EA; Cap_F: 22µF; Value1: Unknown; VDC_V: 16V; TaMin_C: -55°C; TaMax_C: 85°C; Cap_Case: 1206; AEC Category: Q200; SizeArea_mm2: 5.12; SizeAreaWB_mm2: 10.92; SizeX_mm: 3.2; SizeY_mm: 1.6; SizeZ_mm: 1.8
C412 = CMP-0007822-2: CAP, CERM, 22 uF, 6.3 V, +/- 20%, X5R, 0805; Manufacturer: TDK; Polarized: N; Value: 22uF; U/M: EA; Cap_F: 22µF; Value1: Unknown; VDC_V: 6.3V; TaMin_C: -55°C; TaMax_C: 85°C; Cap_Case: 0805; SizeArea_mm2: 2.5; SizeAreaWB_mm2: 6.75; SizeX_mm: 2; SizeY_mm: 1.25; SizeZ_mm: 1.45; AEC Category: Q200
C421 = CMP-0006356-2: CAP, CERM, 0.1 uF, 50 V, +/- 10%, X7R, AEC-Q200 Grade 1, 0402; Manufacturer: MuRata; Polarized: N; Value: 0.1uF; U/M: EA; Cap_F: 100nF; Value1: Unknown; VDC_V: 50V; TaMin_C: -55°C; TaMax_C: 125°C; AEC Category: Q200; AEC Qualified: Y; AEC Grade: 1; SizeArea_mm2: 0.5; SizeAreaWB_mm2: 3; SizeZ_mm: 0.6
C422 C452 = CMP-0006356-2: CAP, CERM, 0.1 uF, 50 V, +/- 10%, X7R, AEC-Q200 Grade 1, 0402; Manufacturer: MuRata; Polarized: N; Value: 0.1uF; U/M: EA; Cap_F: 100nF; Value1: Unknown; VDC_V: 50V; TaMin_C: -55°C; TaMax_C: 125°C; SizeArea_mm2: 0.5; SizeAreaWB_mm2: 3; SizeX_mm: 1; SizeZ_mm: 0.6; AEC Category: Q200; AEC Qualified: Y
C451 C461 C471 = CMP-0006356-2: CAP, CERM, 0.1 uF, 50 V, +/- 10%, X7R, AEC-Q200 Grade 1, 0402; PartNumber: GCM155R71H104KE02D; Manufacturer: MuRata; Polarized: N; Value: 0.1uF; U/M: EA; Cap_F: 100nF; Value1: Unknown; VDC_V: 50V; TaMin_C: -55°C; TaMax_C: 125°C; AEC Category: Q200; AEC Qualified: Y; AEC Grade: 1; SizeArea_mm2: 0.5; SizeAreaWB_mm2: 3; SizeZ_mm: 0.6
C462 C472 = CMP-0006356-2: CAP, CERM, 0.1 uF, 50 V, +/- 10%, X7R, AEC-Q200 Grade 1, 0402; PartNumber: GCM155R71H104KE02D; Manufacturer: MuRata; Polarized: N; Value: 0.1uF; U/M: EA; Cap_F: 100nF; Value1: Unknown; VDC_V: 50V; TaMin_C: -55°C; TaMax_C: 125°C; SizeArea_mm2: 0.5; SizeAreaWB_mm2: 3; SizeX_mm: 1; SizeZ_mm: 0.6; AEC Category: Q200; AEC Qualified: Y
C490 = CMP-0007007-5: CAP, CERM, 10 uF, 25 V, +/- 20%, X5R, 0603; Manufacturer: TDK; Polarized: N; Value: 10uF; U/M: EA; Cap_F: 10µF; ESR_ohm: 4.639m; Value1: 0.004639 ohm; VDC_V: 25V; IRMS_A: 2.41407A; TaMin_C: -55°C; TaMax_C: 85°C; SizeArea_mm2: 1.28; SizeAreaWB_mm2: 4.68; SizeX_mm: 1.6; SizeY_mm: 0.8; SizeZ_mm: 1; AEC Category: Q200
C491 = CMP-0007828-2: CAP, CERM, 10 uF, 25 V, +/- 10%, X5R, 0805; Manufacturer: TDK; Polarized: N; Value: 10uF; U/M: EA; Cap_F: 10µF; Value1: Unknown; VDC_V: 25V; TaMin_C: -55°C; TaMax_C: 85°C; AEC Category: Q200; SizeArea_mm2: 2.5; SizeAreaWB_mm2: 6.75; SizeX_mm: 2; SizeY_mm: 1.25; SizeZ_mm: 1.45
C493 C494 = CMP-0007091-5: CAP, CERM, 2.2 uF, 10 V, +/- 10%, X5R, AEC-Q200 Grade 3, 0603; Manufacturer: TDK; TaMin_C: -55°C; Polarized: N; SizeAreaWB_mm2: 4.68; Value1: Unknown; U/M: EA; Value: 2.2uF; TaMax_C: 85°C; SizeZ_mm: 1; SizeX_mm: 1.6; SizeY_mm: 0.8; SizeArea_mm2: 1.28; AEC Qualified: Y; Cap_F: 2.2µF; AEC Grade: 3; AEC Category: Q200
FID1-FID3 = CMP-0077181-1: Fiducial mark.  There is nothing to buy or mount.
H1-H4 = CMP-0003617-1: Machine Screw, Round, #4-40 x 1/4, Nylon, Philips panhead; Manufacturer: B&F Fastener Supply; CompType: Hardware
H5-H8 = CMP-0003610-1: Standoff, Hex, 0.5"L #4-40 Nylon; Manufacturer: Keystone; CompType: Hardware
J400 = CMP-0074910-1: as J450 on sheet TPS650861&Outputs
J401 = CMP-0075410-2: Header, 100mil, 5x2, Gold, TH; Manufacturer: Samtec; Pitch_mm: 2.54; Gender: Male; Shrouded: N; Row_Count: 2; Current_A: 6.3A; Voltage_V: 550V; Cert_CSA: Y; Green_Lifecycle: Active; Green_REACh: Passed
J421 = CMP-0054947-1: Header, 100mil, 2x1, Gold, TH; Manufacturer: TE Connectivity; Green_Lifecycle: Active; Green_REACh: Passed; CNHeader: TRUE; CT: FALSE
J422 J423 J452 J453 J462 J463 J472 J473 = CMP-0075320-1: Receptacle, Ultra Miniature Coaxial, Male Pin, 50 ohm, SMT; Manufacturer: Hirose Electric Co. Ltd.; CNHeader: False; Gender: Female; ContactFinish: Gold
J451 J461 J471 = CMP-0054947-1: Header, 100mil, 2x1, Gold, TH; PartNumber: 5-146261-1; Manufacturer: TE Connectivity; Green_Lifecycle: Active; Green_REACh: Passed; CNHeader: TRUE; CT: FALSE
J491-J496 = CMP-0075405-3: as J99 on sheet TPS650861&Outputs
L400 = CMP-0059700-1: Inductor, 55 nH, 30 A, 0.0002 ohm, SMD; Manufacturer: Delta Electronics Inc.; Value: 55nH; Imax_A: 30A; Irms: 30A @ 45C rise; DCR_ohm: 200µ; AEC Category: Q200; Green_Lifecycle: Not Set; Green_REACh: Incomplete; SizeArea_mm2: 31.35; SizeAreaWB_mm2: 57.75; SizeX_mm: 5.5; SizeY_mm: 5.7; SizeZ_mm: 4.6
L410 = CMP-0061170-1: Inductor, Shielded, Composite, 2.2 uH, 1.3 A, 0.16 ohm, SMD; Manufacturer: Coilcraft; Value: 2.2uH; Ind_H: 2.2µH; Imax_A: 1.3A; Irms: 1.3A @ 40C rise; Isat: 1.35A @ 30% inductance drop; DCR_ohm: 1.6d; AEC Category: Q200; Green_Lifecycle: Not Set; Green_REACh: Incomplete; SizeArea_mm2: 3.8; SizeAreaWB_mm2: 8.7; SizeX_mm: 2; SizeY_mm: 1.9; SizeZ_mm: 1
LBL1 = CMP-0003625-1: Thermal Transfer Printable Labels, 0.650" W x 0.200" H - 10,000 per roll; Manufacturer: Brady; CompType: Label
Logo1 = CMP-0074838-1: Texas Instrument Corporate Signature; SymbolCreator: a0412235; Lib Reference: TI_Logo; Library Reference: Logo
Logo2 = CMP-0074844-1: SymbolCreator: a0412235
Logo4 = CMP-0074769-1
Q420 = CMP-0000593-2: MOSFET, N-CH, 30 V, 20 A, DNH0008A (VSONP-8); Manufacturer: Texas Instruments; Alternate Manufacturer: None; ChType: N; Value: 30V; Value1: 0.014; Rdson45_ohm: 0.0142; Value2: 5.3 nC; QgTyp_nC: 5.3; Vgs_V: 20V; IdsMax_A: 20A; SizeAreaWB_mm2: 18.49; SizeArea_mm2: 10.89; SizeX_mm: 3.3; SizeZ_mm: 0.9; AEC Category: Q101; ChMode: Enhancement
Q450 Q460 Q470 = CMP-0000248-1: MOSFET, N-CH, 25 V, 5 A, DQK0006C (WSON-6); Manufacturer: Texas Instruments; Alternate Manufacturer: None; U/M: EA; ChType: N; Value: 25V; Value1: 0.02; Rdson45_ohm: 0.023; Value2: 2 nC; QgTyp_nC: 2; Vgs_V: 10V; IdsMax_A: 5A; SizeAreaWB_mm2: 9; SizeArea_mm2: 4; SizeZ_mm: 0.8; AEC Category: Q101
R401-R404 = CMP-0025701-4: RES, 10 k, 5%, 0.1 W, AEC-Q200 Grade 0, 0603; Manufacturer: Vishay-Dale; Value_Code: 10k0; Power_W: 100mW; Value2: 0.1W; VDC_V: 75V; TempCo: 200 ppm/C; EIA_Code: E24; AEC Category: Q200; AEC Grade: 0; AEC Qualified: Y; SizeArea_mm2: 1.28; SizeX_mm: 1.6; SizeY_mm: 0.8; SizeZ_mm: 1
R421 R451 R461 R471 = CMP-0026866-3: RES, 1.0, 5%, 0.063 W, AEC-Q200 Grade 0, 0402; PartNumber: CRCW04021R00JNED; Manufacturer: Vishay-Dale; Value: 1.0; Res_ohm: 1; Value_Code: 1R00; Power_W: 63mW; Value2: 0.063W; VDC_V: 50V; TempCo: 200 ppm/C; EIA_Code: E24; AEC Category: Q200; AEC Qualified: Y; AEC Grade: 0; SizeArea_mm2: 0.5; SizeZ_mm: 0.6
R422 R452 R462 R472 = CMP-0025958-3: RES, 10.0 k, 1%, 0.063 W, AEC-Q200 Grade 0, 0402; PartNumber: CRCW040210K0FKED; Manufacturer: Vishay-Dale; Value: 10.0k; Res_ohm: 10k; Value_Code: 10k0; Power_W: 63mW; Value2: 0.063W; VDC_V: 50V; TempCo: 100 ppm/C; EIA_Code: E96; AEC Category: Q200; AEC Qualified: Y; AEC Grade: 0; SizeArea_mm2: 0.5; SizeX_mm: 1; SizeZ_mm: 0.6
R423 R424 R429 R453 R454 R463 R464 = CMP-0016745-3: RES, 1.00, 1%, 0.25 W, AEC-Q200 Grade 0, 1206; PartNumber: CRCW12061R00FKEA; Manufacturer: Vishay-Dale; Value: 1.00; Res_ohm: 1; Value_Code: 1R00; Power_W: 250mW; Value2: 0.25W; VDC_V: 200V; TempCo: 100 ppm/C; SizeArea_mm2: 5.12; SizeX_mm: 3.2; SizeY_mm: 1.6; SizeZ_mm: 1.35; EIA_Code: E96; AEC Category: Q200; AEC Qualified: Y; AEC Grade: 0
R425 R455 R465 = CMP-0026404-2: RES, 49.9, 1%, 0.063 W, AEC-Q200 Grade 0, 0402; PartNumber: CRCW040249R9FKED; Manufacturer: Vishay-Dale; Value: 49.9; Value_Code: 49R9; Power_W: 63mW; Value2: 0.063W; VDC_V: 50V; TempCo: 100 ppm/C; EIA_Code: E96; AEC Category: Q200; AEC Qualified: Y; AEC Grade: 0; SizeArea_mm2: 0.5; SizeX_mm: 1; SizeZ_mm: 0.6
R426 R456 R466 = CMP-0026404-2: RES, 49.9, 1%, 0.063 W, AEC-Q200 Grade 0, 0402; PartNumber: CRCW040249R9FKED; Manufacturer: Vishay-Dale; Value: 49.9; Value_Code: 49R9; Power_W: 63mW; Value2: 0.063W; VDC_V: 50V; TempCo: 100 ppm/C; EIA_Code: E96; SizeArea_mm2: 0.5; SizeX_mm: 1; SizeZ_mm: 0.6; AEC Category: Q200; AEC Qualified: Y; AEC Grade: 0
R473 = CMP-0016583-3: RES, 10.0, 1%, 0.25 W, AEC-Q200 Grade 0, 1206; Manufacturer: Vishay-Dale; Value: 10.0; Res_ohm: 10; Value_Code: 10R0; Power_W: 250mW; Value2: 0.25W; VDC_V: 200V; TempCo: 100 ppm/C; SizeArea_mm2: 5.12; SizeX_mm: 3.2; SizeY_mm: 1.6; SizeZ_mm: 1.35; EIA_Code: E96; AEC Category: Q200; AEC Qualified: Y; AEC Grade: 0
R475 = CMP-0026404-2: RES, 49.9, 1%, 0.063 W, AEC-Q200 Grade 0, 0402; Manufacturer: Vishay-Dale; Value: 49.9; Value_Code: 49R9; Power_W: 63mW; Value2: 0.063W; VDC_V: 50V; TempCo: 100 ppm/C; EIA_Code: E96; AEC Category: Q200; AEC Qualified: Y; AEC Grade: 0; SizeArea_mm2: 0.5; SizeX_mm: 1; SizeZ_mm: 0.6
R476 = CMP-0026404-2: RES, 49.9, 1%, 0.063 W, AEC-Q200 Grade 0, 0402; Manufacturer: Vishay-Dale; Value: 49.9; Value_Code: 49R9; Power_W: 63mW; Value2: 0.063W; VDC_V: 50V; TempCo: 100 ppm/C; EIA_Code: E96; SizeArea_mm2: 0.5; SizeX_mm: 1; SizeZ_mm: 0.6; AEC Category: Q200; AEC Qualified: Y; AEC Grade: 0
R490 = CMP-0025697-4: RES, 0, 5%, 0.1 W, AEC-Q200 Grade 0, 0603; Manufacturer: Vishay-Dale; Value: 0; Value_Code: 0000; Power_W: 100mW; Value2: 0.1W; VDC_V: 75V; TempCo: 200 ppm/C; EIA_Code: E24; SizeArea_mm2: 1.28; SizeX_mm: 1.6; SizeY_mm: 0.8; SizeZ_mm: 1; AEC Category: Q200; AEC Qualified: Y
R491 R493 = CMP-0021990-4: RES, 100 k, 1%, 0.1 W, AEC-Q200 Grade 0, 0603; Manufacturer: Vishay-Dale; Value: 100k; Power_W: 100mW; Value2: 0.1W; VDC_V: 75V; TempCo: 100 ppm/C; EIA_Code: E96; AEC Category: Q200; AEC Grade: 0; AEC Qualified: Y; SizeArea_mm2: 1.28; SizeX_mm: 1.6; SizeY_mm: 0.8; SizeZ_mm: 1
R494 = CMP-0026407-2: RES, 4.22 k, 1%, 0.063 W, AEC-Q200 Grade 0, 0402; Manufacturer: Vishay-Dale; Power_W: 63mW; TempCo: 100 ppm/C; Value_Code: 4k22; Value: 4.22k; EIA_Code: E96; SizeX_mm: 1; SizeY_mm: 0.5; SizeZ_mm: 0.6; Value2: 0.063W; AEC Qualified: Y; VDC_V: 50V; AEC Category: Q200; AEC Grade: 0
R495 = CMP-0025958-3: as R65 on sheet TPS650861&Outputs
TP400 = CMP-0055137-1: as TP211 on sheet TPS650861&Outputs
TP401 = CMP-0055138-1: as TP212 on sheet TPS650861&Outputs
TP490 = CMP-0055142-1: Test Point, Compact, Red, TH; Manufacturer: Keystone; ContactFinish: Silver; CNHeader: FALSE; CT: TRUE; Green_Lifecycle: Active; Green_REACh: Passed
U490 = CMP-0037799-2: Buck Step Down Regulator with 3 to 17 V Input and 5 V Output, -40 to 85 degC, 8-Pin WSON (DSG), Green (RoHS & no Sb/Br); Manufacturer: Texas Instruments; Duty Cycle(Max)(%): 100; Iout(Max)(A): 0.5; Iq(Typ)(mA): 0.017; Preset Vout(V): 5; Rating: Catalog; Regulated Outputs(#): 1; SubFamily: Step-Down Regulator; Switch Current Limit(Typ)(A): 1.05; Synchronous Rectification: TRUE; Vin(Max)(V): 17; Vin(Min)(V): 3
U491 = CMP-0082614-1: 500-mA LDO With Power-Good, DRV0006A (WSON-6); Alternate PartNumber: TPS74501PDRVT; Alternate Manufacturer: Texas Instruments; SizeAreaWB_mm2: 9; SizeZ_mm: 0.8; SizeX_mm: 2; SizeArea_mm2: 4; CompType: IC; AEC Qualified: N; AEC Category: Q200
ZZ1 = CMP-0003616-3
ZZ2 = CMP-0077236-1
ZZ3 = CMP-0077237-1
ZZ4 = CMP-0077238-1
